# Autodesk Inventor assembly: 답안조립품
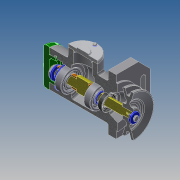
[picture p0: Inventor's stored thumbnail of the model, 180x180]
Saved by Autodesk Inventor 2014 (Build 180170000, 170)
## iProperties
Created: 2017-10
Part Number: 답안조립품
Document SubType Name: Assembly
Designer: kb543-11
Author: kb543-11
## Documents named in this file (20)
- C:\Users\kb543-11\Desktop\471007V1035\답안조립품.iam
- C:\Users\kb543-11\Desktop\471007V1035\1-본체.ipt
- C:\Users\kb543-11\Desktop\471007V1035\축.ipt
- C:\Users\kb543-11\Desktop\471007V1035\부시1.ipt
- C:\Users\kb543-11\Desktop\471007V1035\베어링 15 x 35 x 11.ipt
- C:\Users\kb543-11\Desktop\471007V1035\멈춤링 15 x 1.ipt
- C:\Users\kb543-11\Desktop\471007V1035\멈춤링 35x1.6.ipt
- C:\Users\kb543-11\Desktop\471007V1035\부시2.ipt
- C:\Users\kb543-11\Desktop\471007V1035\와셔 10x21.ipt
- C:\Users\kb543-11\Desktop\471007V1035\너트 M10.ipt
- C:\Users\kb543-11\Desktop\471007V1035\키 4 x 4 x 18.ipt
- C:\Users\kb543-11\Desktop\471007V1035\V-벨트풀리.ipt
- C:\Users\kb543-11\Desktop\471007V1035\와셔 4x16.ipt
- C:\Users\kb543-11\Desktop\471007V1035\볼트 M4 x 10.ipt
- C:\Users\kb543-11\Desktop\471007V1035\오일 실 15 25 7.ipt
- C:\Users\kb543-11\Desktop\471007V1035\사이드 커버.ipt
- 사이드 커버.ipt
- C:\Users\kb543-11\Desktop\471007V1035\탑 커버.ipt
- C:\Users\kb543-11\Desktop\471007V1035\와셔 3x6.ipt
- C:\Users\kb543-11\Desktop\471007V1035\십자볼트 M3 x 10.ipt
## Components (3 placed, 3 different names)
1. 1-본체:1 — 플러쉬:2, 각도:1
2. V-벨트풀리:1
3. ISO 4017 M4 x 10:1
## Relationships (2: Flush 1, Angle 1)
- 플러쉬:2 [Flush]: 1-본체:1
- 각도:1 [Angle]: 1-본체:1
